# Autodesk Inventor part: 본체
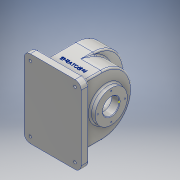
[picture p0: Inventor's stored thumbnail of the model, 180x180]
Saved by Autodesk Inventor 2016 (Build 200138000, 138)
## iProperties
Created: 2017-11
Part Number: 본체
Material: 알루미늄 6061
Document SubType Name: Modeling
Designer: 605-03
Mass: 2182.82 g
Surface Area: 1149.28 cm^2
Volume: 808.452 cm^3
Density: 2.7 g/cm^3
Appearance: 알루미늄 - 평지
Author: 605-03
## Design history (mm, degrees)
sketch "스케치1"
  geometry: L1 (0, 0)-(-80, 0); L2 (-80, 0)-(-80, -72); L3 (-80, 0)-(-80, 72); L4 (0, -58)-(-80, -58); L5 (0, 58)-(-80, 58); A1 r 58 centre (0, 0) between (0, -58) and (0, 58); 1 further point
  constraints: 10 end point, 2 perpendicular, 2 point on circle, 2 point on line, 2 vertical, 1 centre point, 1 coincident, 1 collinear, 1 horizontal
  dimensions: "d0" = 116 diameter of A1; "d2" = 80 distance of L1.start L1.end; "d5" = 72 distance of L1.end L2.end; "d6" = 80 distance of L4.start L4.end; "d7" = 80 distance of L5.start L5.end
extrude "돌출1" new body sketch "스케치1" distance "d8" = 38; taper "d9" = 0 deg
sketch "스케치2"
  geometry: L1 (0, 0)-(0, -23); L2 (-58, -80)-(58, -80) reference; L3 (58, -80)-(58, 0) reference; L4 (-58, 0)-(-58, -80) reference; L5 (58, -80)-(58, 0) reference; L6 (-58, -80)-(58, -80) reference; L7 (58, -23)-(58, -80); L8 (58, -80)-(-58, -80); L9 (-58, -80)-(-58, -23); L10 (-58, 0)-(-58, -80) reference; A1 r 58 centre (0, -23) between (58, -23) and (-58, -23); A2 r 58 centre (0, 0) between (58, 0) and (-58, 0) reference
  constraints: 8 end point, 2 point on circle, 2 point on line, 2 vertical, 1 centre point, 1 coincident, 1 collinear
  dimensions: "d10" = 23 distance of L1.start L1.end; "d11" = 116 diameter of A1
extrude "돌출2" join sketch "스케치2" distance "d12" = 38; taper "d13" = 0 deg
sketch "스케치3"
  geometry: L1 (-5, 133)-(81, 133); L2 (93, 121)-(93, -5); L3 (81, -17)-(-5, -17); L4 (-17, -5)-(-17, 121); L5 (38, 0)-(38, 116) reference; L6 (-17, 133)-(93, -17); L7 (93, 133)-(-17, -17); A1 r 12 centre (-5, 121) between (-5, 133) and (-17, 121); A2 r 12 centre (81, 121) between (93, 121) and (81, 133); A3 r 12 centre (81, -5) between (81, -17) and (93, -5); A4 r 12 centre (-5, -5) between (-17, -5) and (-5, -17); 2 further points
  constraints: 12 end point, 8 point on circle, 8 point on line, 8 tangent, 4 centre point, 3 midpoint, 2 parallel, 1 horizontal, 1 perpendicular
  dimensions: "d14" = 110 distance of L6.end L7.end; "d15" = 150 distance of L7.start L6.end; "d16" = 12 radius of A1; "d17" = 12 radius of A2; "d18" = 12 radius of A3; "d19" = 12 radius of A4
extrude "돌출3" join sketch "스케치3" distance "d20" = 15; taper "d21" = 0 deg
sketch "스케치4"
  geometry: L1 (-58, -23)-(-58, -65) reference; L2 (-58, -23)-(58, -23); C1 r 31 at (0, -15); C2 r 16 at (0, -15); 1 further point
  constraints: 2 centre point, 2 end point, 1 coincident, 1 horizontal, 1 vertical alignment
  dimensions: "d22" = 62 diameter of C1; "d24" = 8 distance from line of L2 C1.centre; "d25" = 32 diameter of C2
extrude "돌출4" join sketch "스케치4" distance "d26" = 10; taper "d27" = 0 deg
sketch "스케치5"
  geometry: 1 further point
sketch "스케치6" dims "d29" = 52
  geometry: L1 (-73.909, -50)-(73.909, -50) reference; L2 (73.909, -50)-(73.909, -65) reference; L3 (73.909, -65)-(-73.909, -65) reference; L4 (-73.909, -65)-(-73.909, -50) reference; C1 r 16 at (0, 0) reference; C2 r 31 at (0, 0) reference; 6 further points
  constraints: 2 vertical alignment, 1 coincident, 7 other
  dimensions: "d32" = 360 deg dimension on C2.centre point (0, 26) (derived)
hole "구멍1" sketch "스케치6" at (0, 26), (26, 0), (0, -26), (-26, 0) diameter "d34" = 2.459; stored, may be unused: countersink angle "d38" = 90 deg, drill point angle "d40" = 118 deg; dims "d35" = 6, "d36" = 4, "d37" = 2, "d39" = 8
sketch "스케치7"
  geometry: L1 (-75, -65)-(-58, -65) reference; L2 (-58, -65)-(58, -65) reference; L3 (58, -65)-(75, -65) reference; L4 (75, -65)-(75, -80) reference; L5 (75, -80)-(-75, -80) reference; L6 (-75, -80)-(-75, -65) reference; L7 (-58, -65)-(-58, 0) reference; L8 (58, 0)-(58, -65) reference; C1 r 37.5 at (0, -15); C2 r 16 at (0, -15); A1 r 58 centre (0, 0) between (58, 0) and (-58, 0) reference; 1 further point
  constraints: 2 centre point, 1 coincident, 1 vertical alignment
  dimensions: "d41" = 75 diameter of C1; "d42" = 15 distance of point (0, 0) C1.centre; "d43" = 32 diameter of C2
extrude "돌출5" join sketch "스케치7" distance "d44" = 9; taper "d45" = 0 deg
sketch "스케치8" dims "d47" = 58
  geometry: L1 (-74.314, -50)-(74.314, -50) reference; L2 (74.314, -50)-(74.314, -65) reference; L3 (74.314, -65)-(-74.314, -65) reference; L4 (-74.314, -65)-(-74.314, -50) reference; C1 r 16 at (0, 0) reference; C2 r 37.5 at (0, 0) reference; 9 further points
  constraints: 3 coincident, 3 vertical alignment, 2 horizontal alignment, 19 other
  dimensions: "d50" = 360 deg dimension on point (0, 0) point (0, 29) (derived)
hole "구멍2" sketch "스케치8" at (0, 29), (29, 0), (0, -29), (-29, 0) diameter "d52" = 2.459; stored, may be unused: countersink angle "d56" = 90 deg, drill point angle "d58" = 118 deg; dims "d53" = 6, "d54" = 4, "d55" = 2, "d57" = 8
node "작업 평면4"
sketch "스케치9"
  geometry: L1 (0, -58)-(0, 58) reference; L2 (0, 58)-(-38, 58) reference; L3 (-38, -58)-(-38, 58) reference; L4 (0, -58)-(-38, -58) reference; C1 r 6 at (-19, 0); 1 further point
  constraints: 1 centre point, 1 horizontal alignment, 1 midpoint
  dimensions: "d64" = 12 diameter of C1; "d65" = 19 distance from line of L1 C1.centre
extrude "돌출6" join sketch "스케치9" stored distance "d66" = 9; taper "d67" = 0 deg
hole "구멍3" diameter "d70" = 4.134; stored, may be unused: countersink angle "d74" = 90 deg, drill point angle "d76" = 118 deg; dims "d68" = 10, "d69" = 10, "d71" = 20, "d72" = 4, "d73" = 2, "d75" = 20
sketch "스케치10"
  geometry: L1 (0, 1)-(0, -31) reference; L2 (0, 0)-(38, 0) reference; L3 (0, 0)-(0, -15); L4 (0, -15)-(76, -15); L5 (76, -31)-(76, 1) reference; L6 (5, 0)-(5, 50); L7 (8, 53)-(30, 53); L8 (36, 30)-(68, 30); L9 (0, 0)-(0, 58) reference; L10 (76, 16)-(86, 16) reference; L11 (86, 16)-(86, 12.23) reference; L12 (86, 12.23)-(78, 12.23) reference; L13 (78, 12.23)-(77.261, 11) reference; L14 (77.261, 11)-(78, 9.771) reference; L15 (78, 9.771)-(86, 9.771) reference; L16 (86, 9.771)-(86, 1) reference; L17 (86, 1)-(76, 1) reference; L18 (76, 1)-(76, -31) reference; L19 (76, -31)-(86, -31) reference; L20 (86, -31)-(86, -39.77) reference; L21 (86, -39.77)-(78, -39.77) reference; L22 (78, -39.77)-(77.261, -41) reference; L23 (77.261, -41)-(78, -42.23) reference; L24 (78, -42.23)-(86, -42.23) reference; L25 (86, -42.23)-(86, -46) reference; L26 (86, -46)-(76, -46) reference; L27 (76, -46)-(76, -65) reference; L28 (76, -65)-(93, -65) reference; L29 (93, -65)-(93, -80) reference; L30 (93, -80)-(-17, -80) reference; L31 (-17, -80)-(-17, -65) reference; L32 (-17, -65)-(0, -65) reference; L33 (0, -65)-(0, -52.5) reference; L34 (0, -52.5)-(-9, -52.5) reference; L35 (-9, -52.5)-(-9, -45.23) reference; L36 (-9, -45.23)-(-1, -45.23) reference; L37 (-1, -45.23)-(-0.261, -44) reference; L38 (-0.261, -44)-(-1, -42.77) reference; L39 (-1, -42.77)-(-9, -42.77) reference; L40 (-9, -42.77)-(-9, -31) reference; L41 (-9, -31)-(0, -31) reference; L42 (0, -31)-(0, 1) reference; L43 (0, 1)-(-9, 1) reference; L44 (-9, 1)-(-9, 12.771) reference; L45 (-9, 12.771)-(-1, 12.771) reference; L46 (-1, 12.771)-(-0.261, 14) reference; L47 (-0.261, 14)-(-1, 15.23) reference; L48 (-1, 15.23)-(-9, 15.23) reference; L49 (-9, 15.23)-(-9, 22.5) reference; L50 (-9, 22.5)-(0, 22.5) reference; L51 (0, 22.5)-(0, 58) reference; L52 (0, 58)-(13, 58) reference; L53 (13, 58)-(13, 64) reference; L54 (13, 64)-(16.933, 64) reference; L55 (16.933, 64)-(16.933, 44) reference; L56 (16.933, 44)-(19, 42.758) reference; L57 (19, 42.758)-(21.067, 44) reference; L58 (21.067, 44)-(21.067, 64) reference; L59 (21.067, 64)-(25, 64) reference; L60 (25, 64)-(25, 58) reference; L61 (25, 58)-(38, 58) reference; L62 (38, 58)-(38, 35) reference; L63 (38, 35)-(76, 35) reference; L64 (76, 35)-(76, 16) reference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; A1 r 3 centre (8, 50) between (8, 53) and (5, 50); A2 r 3 centre (30, 50) between (33, 50) and (30, 53); A3 r 3 centre (36, 33) between (33, 33) and (36, 30); A4 r 3 centre (68, 27) between (71, 27) and (68, 30)
  constraints: 16 end point, 8 point on circle, 8 tangent, 4 centre point, 3 equal radius, 3 vertical, 2 midpoint, 2 point on line, 1 horizontal, 1 perpendicular
  dimensions: "d78" = 15 distance of L2.start L3.end; "d79" = 5 distance between parallel lines of L9 L6; "d82" = 5 distance between parallel lines of L52 L7; "d83" = 5 distance between parallel lines of L8 L63; "d85" = 5 distance between parallel lines of L62 L65; "d86" = 5 distance between parallel lines of L7 L61 (derived); "d88" = 5 distance between parallel lines of L64 L66; "d89" = 3 radius of A1
revolve "회전1" sketch "스케치10" stored, may be unused: angle "d90" = 90 deg
extrude "돌출7" cut sketch "스케치4" distance "d91" = 158.25; taper "d92" = 0 deg
fillet "모깎기1" dims "d93" = 3
chamfer "모따기1" distance "d94" = 1; stored, may be unused: second distance "d95" = 2, angle "d96" = 45 deg
hole "구멍4" diameter "d99" = 5; stored, may be unused: countersink angle "d103" = 90 deg, drill point angle "d105" = 0 deg; dims "d97" = 10, "d98" = 10, "d100" = 20, "d101" = 4, "d102" = 2, "d104" = 12
hole "구멍5" diameter "d108" = 5; stored, may be unused: countersink angle "d112" = 90 deg, drill point angle "d114" = 0 deg; dims "d106" = 10, "d107" = 10, "d109" = 20, "d110" = 4, "d111" = 2, "d113" = 12
hole "구멍6" diameter "d117" = 5; stored, may be unused: countersink angle "d121" = 90 deg, drill point angle "d123" = 0 deg; dims "d115" = 10, "d116" = 10, "d118" = 20, "d119" = 4, "d120" = 2, "d122" = 12
hole "구멍7" diameter "d126" = 5; stored, may be unused: countersink angle "d130" = 90 deg, drill point angle "d132" = 0 deg; dims "d124" = 10, "d125" = 10, "d127" = 20, "d128" = 4, "d129" = 2, "d131" = 12
hole "구멍8" diameter "d135" = 12; stored, may be unused: countersink angle "d139" = 90 deg, drill point angle "d141" = 0 deg; dims "d133" = 10, "d134" = 10, "d136" = 20, "d137" = 4, "d138" = 2, "d140" = 5
hole "구멍9" diameter "d144" = 12; stored, may be unused: countersink angle "d148" = 90 deg, drill point angle "d150" = 0 deg; dims "d142" = 10, "d143" = 10, "d145" = 20, "d146" = 4, "d147" = 2, "d149" = 5
hole "구멍10" diameter "d153" = 12; stored, may be unused: countersink angle "d157" = 90 deg, drill point angle "d159" = 0 deg; dims "d151" = 10, "d152" = 10, "d154" = 20, "d155" = 4, "d156" = 2, "d158" = 5
hole "구멍11" diameter "d162" = 12; stored, may be unused: countersink angle "d166" = 90 deg, drill point angle "d168" = 0 deg; dims "d160" = 10, "d161" = 10, "d163" = 20, "d164" = 4, "d165" = 2, "d167" = 5
sketch "스케치11" dims "d2" = 80
  geometry: L1 (-3, 62)-(-3, 0) reference; L2 (78, -18)-(-8, -18) reference; 1 further point
  constraints: 1 other
  dimensions: "d169" = 38 distance from line of point (35, 22) L1; "d170" = 40 distance from line of L2 point (35, 22)
feature "엠보싱1" sketch "스케치11" dims "d0" = 116, "d2" = 80, "d5" = 72, "d6" = 80, "d7" = 80, "d171" = 0.5, "d172" = 0
node "솔리드1"
node "투영된 루프1"
node "투영된 루프2"
node "절단 모서리 투영1"
node "절단 모서리 투영2"
node "절단 모서리 투영3"
node "절단 모서리 투영4"
